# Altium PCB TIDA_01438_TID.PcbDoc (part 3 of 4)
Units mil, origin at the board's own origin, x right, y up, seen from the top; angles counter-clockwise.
Board outline 6250 x 2150 mil, 4 copper layers (Top Layer, V-, V+, Bottom Layer), stack 61.6 mil thick; 360 components, 217 nets, 1141 pads, 401 vias.
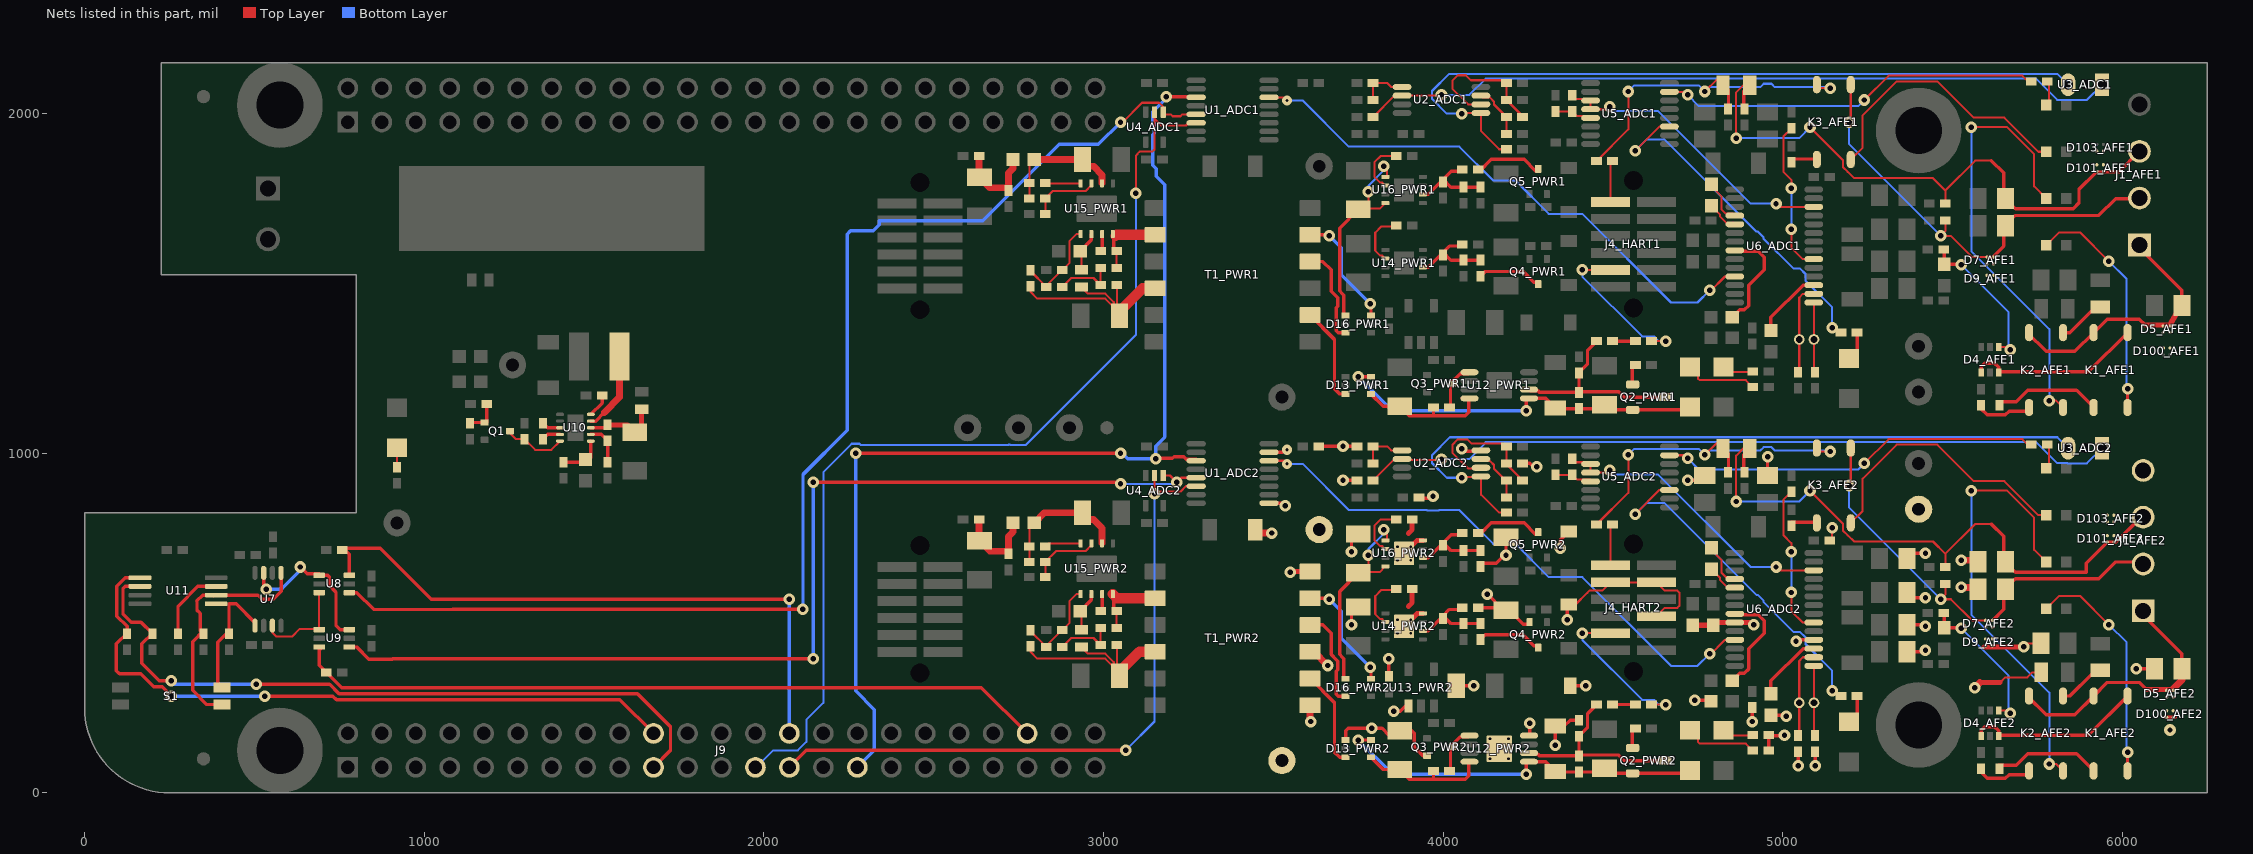
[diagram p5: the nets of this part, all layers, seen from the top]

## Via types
v1: diameter 34, hole 16, Top Layer to Bottom Layer, 337 vias
v2: diameter 19.68, hole 7.87, Top Layer to Bottom Layer, 36 vias
v3: diameter 39.37, hole 19.68, Top Layer to Bottom Layer, 24 vias
v4: diameter 30, hole 10, Top Layer to Bottom Layer, 4 vias

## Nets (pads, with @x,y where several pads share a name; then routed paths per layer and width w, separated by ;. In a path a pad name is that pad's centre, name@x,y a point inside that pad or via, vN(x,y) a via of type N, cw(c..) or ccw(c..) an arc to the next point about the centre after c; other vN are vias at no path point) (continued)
GND_ADC2: C1_ADC2.2 C4_ADC2.2 C6_ADC2.2 C7_ADC2.2 C8_ADC2.2 C12_ADC2.2 C13_ADC2.2 C14_ADC2.2 C16_ADC2.2 C17_AFE2.2 C19_AFE2.1 C20_AFE2.2 C21_AFE2.2 C22_AFE2.2 C23_AFE2.2 C25_AFE2.1 C27_AFE2.2 C28_AFE2.2 C30_AFE2.1 C40_PWR2.2 C41_PWR2.2 C43_PWR2.2 C44_PWR2.2 C46_PWR2.2 C47_PWR2.2 C48_PWR2.2 C52_PWR2.2 C58_PWR2.2 C59_PWR2.2 C61_PWR2.1 D9_AFE2.B1 D9_AFE2.B2 D13_PWR2.1 D15_PWR2.2 D17_PWR2.2 D18_PWR2.1 D100_AFE2.B1 D100_AFE2.B2 D103_AFE2.B1 D103_AFE2.B2 J1_AFE2.4 J4_HART2.3 J4_HART2.4 J4_HART2.8 Q3_PWR2.2 Q4_PWR2.2 R7_ADC2.1 R8_ADC2.2 R9_ADC2.1 R19_AFE2.1 R27_AFE2.1 R50_PWR2.1 R53_PWR2.1 R54_PWR2.2 R56_PWR2.1 R69_PWR2.1 T1_PWR2.7 T1_PWR2.9 T1_PWR2.12 TP4_AFE2.1 TP5_AFE2.1 TP6_AFE2.1 U1_ADC2.9 U1_ADC2.15 U2_ADC2.4 U6_ADC2.9 U6_ADC2.18 U12_PWR2.4 U12_PWR2.9 U13_PWR2.1 U14_PWR2.4 U14_PWR2.9 U16_PWR2.4 U16_PWR2.9 | length 4395
  Top Layer w6: D17_PWR2.2@4370,554.48 4389.47,554.47 4424.07,589.07 4424.13,589.07 4430.5,595.44 4467.92,595.44 J4_HART2.3@4492.48,620 J4_HART2.4@4627.52,620 4652.08,595.44 4689.5,595.44 4695.87,589.07 4695.87,550.93 4689.5,544.56 4652.08,544.56 J4_HART2.8@4627.52,520 ; R27_AFE2.1@5138.62,742.76 5145,749.13 v1(5145,780) ; 5640,325 5655,340 5720,340 5735,355 R19_AFE2.1@5760.63,355 ; v1@5710,440 C21_AFE2.2@5760,440
  Top Layer w10: U1_ADC2.9@3487.28,852.82 3537.5,852.82 3535,850.32 v1(3535,845) ; U1_ADC2.15@3487.28,1002.82 3527.5,1002.82 3540,1015.32 v4(3540,1010.32) ; v1@3607.95,212.05 v1(3610,210) ; C1_ADC2.2@3633.62,1020 v1(3705,1020) R8_ADC2.2@3746.38,1020 ; v1(3705,920) R7_ADC2.1@3746.38,920 ; D13_PWR2.1@3712.6,155.59 3712.6,182.6 3720,190 v1(3790,190) 3820,190 3840,170 3871.86,201.86 C41_PWR2.2@3871.86,182.9 3907.1,182.9 3915,175 3915,135 3940.59,109.41 Q3_PWR2.2@3958.5,109.41 ; v1(3730,495) 3730,545 3750,565 C47_PWR2.2@3750,547.09 ; v1(3730,710) 3730,745 3754.59,769.59 3762.09,762.09 C58_PWR2.2@3750,762.09 ; C43_PWR2.2@3840,341.5 3835,346.5 3840,351.5 v1(3840,395) ; U16_PWR2.9@3885,705 v2(3904.69,724.68) ; U13_PWR2.1@3897.6,255.87 3890,255.87 3874.13,240 v1(3855,240) ; C4_ADC2.2@3928.62,867.74 v1@3970,867.74 ; C44_PWR2.2@4037.91,315 v1(4090,315) ; v1(4055,1012.74) 4060,1012.74 4066.61,1006.13 U2_ADC2.4@4111.14,1006.13 ; R56_PWR2.1@4103.62,545 C46_PWR2.2@4170,545 ; R69_PWR2.1@4110,666.38 4110,676.38 4156.38,676.38 4185,705 C52_PWR2.2@4185,752.09 ; v1(4130,585) 4135,585 4135,580 C46_PWR2.2@4170,545 ; C46_PWR2.2@4185,537.09 4182.91,537.09 4175,545 C46_PWR2.2@4170,545 ; C46_PWR2.2@4190,542.09 4235.59,496.5 Q4_PWR2.2@4254.41,496.5 ; R9_ADC2.1@4233.62,970 4255,970 v1@4269.31,955.69 ; U12_PWR2.4@4252.6,168.39 4251.61,168.39 4255,171.77 v1(4255,205) ; v1@4270,955 v1@4269.31,955.69 ; v1(4275,960) 4275,961.38 v1@4269.31,955.69 ; v1(4330,140) C40_PWR2.2@4330,196.93 4356.93,196.93 4373.62,213.62 R53_PWR2.1@4400,213.62 R53_PWR2.1@4393.62,220 ; v1(4345,720) 4345,744.47 D18_PWR2.1@4370,769.47 ; v1(4365,510) 4365,549.47 D17_PWR2.2@4370,554.48 ; D15_PWR2.2@4374.46,315 v1(4420,315) ; v1(4720,920) 4755,920 C28_AFE2.2@4770,935 C28_AFE2.2@4775,935 ; v1(4741.09,273.13) 4785.38,273.13 C6_ADC2.2@4788.5,270 ; v1(4910,210) 4910,244.07 C7_ADC2.2@4911.3,245.37 ; C30_AFE2.1@4950,945 4950,935 C30_AFE2.1@4955,935 v1(4955,990) ; R50_PWR2.1@4958.62,125 R54_PWR2.2@4958.62,170 4960,168.62 5003.62,168.62 v1(5005,170) ; C16_ADC2.2@4965,228.5 5006.5,228.5 v1(5010,225) ; v1(5038.9,446.15) 5038.9,448.9 5040.43,450.43 U6_ADC2.18@5091.14,450.43 ; v1(5045,80) C12_ADC2.2@5045,121.38 ; v1(5095,80) C13_ADC2.2@5095,121.38 ; C25_AFE2.1@5350.01,690.01 C25_AFE2.1@5370,710 ; C17_AFE2.2@5364.45,393.52 5364.45,400 C17_AFE2.2@5364.45,403.52 ; C19_AFE2.1@5364.45,503.52 C19_AFE2.1@5364.45,508.49 ; C17_AFE2.2@5365,415 5420,415 v1(5420,420) ; C19_AFE2.1@5365,495 5420,495 v1(5420,490) ; C22_AFE2.2@5365,590 5370.03,584.97 5370.03,570 5380.03,580 5385.03,575 v1(5420,575) ; C25_AFE2.1@5365,690 5370,690 5385,705 v1(5420,705) ; v1@5706.84,433.16 v1(5710,430) ; v1(6040,365) C20_AFE2.2@6095,365 ; 6124.62,222.4 6155.22,222.4 ; v1(3855,240) 3854.57,239.57 3855,239.13 v1(3855,240)
  Top Layer w15: v1(3550,650) 3551.85,651.85 T1_PWR2.12@3607.95,651.85 ; U14_PWR2.9@3885,490 3923.39,528.39 U14_PWR2.4@3940.12,528.39 ; 3897.8,549.06 3908.62,559.88 C48_PWR2.2@3908.62,600 ; 3897.8,764.06 3908.62,774.88 C59_PWR2.2@3908.62,805 ; v2(3904.69,724.68) 3923.39,743.39 U16_PWR2.4@3940.12,743.39 ; C8_ADC2.2@4735,493.5 C14_ADC2.2@4795,493.5 4803.11,501.61 U6_ADC2.9@4858.86,501.61 4903.39,501.61 4910,495 v1(4915,495) ; 5580,325 5640,325 ; 5592.36,429 v1@5705,429
  Top Layer w20: C61_PWR2.1@3446.95,765 v1(3495,765) ; v1@3607.95,212.05 T1_PWR2.7@3607.95,258.15 ; T1_PWR2.9@3607.95,415.63 3619.37,415.63 v1(3660,375) ; v1(5525,605) C23_AFE2.2@5575,605 ; v1(5525,685) C27_AFE2.2@5575,685 ; v1(5565,310) 5580,325
  other v1: 6140,185 4185,700 3970,872.74
  other v2: 4137.83,100.87 4192.17,100.87 4165,130 4137.83,159.13 4192.17,159.13 3865.31,470.32 3904.69,470.32 3865.31,509.68 3904.69,509.68 3865.31,685.32 3904.69,685.32 3865.31,724.68
GPIO2_ADC1: R11_ADC1.1 U5_ADC1.11 U5_ADC1.12 U6_ADC1.26 | length 868.8
  Top Layer w6: R11_ADC1.1@4380,2053.62 4390.24,2043.39 4433.86,2043.39 U5_ADC1.11@4433.86,2038.39 U5_ADC1.12@4433.86,2017.8 ; U5_ADC1.12@4433.86,2012.8 v1@4492.8,2012.8 ; v1(4980,1735) 4989.84,1725.16 U6_ADC1.26@5091.14,1725.16
  Bottom Layer w6: v1(4490,2020) 4490,2015 4497.13,2007.87 4632.13,2007.87 4905,1735 v1(4980,1735)
GPIO2_ADC2: R11_ADC2.1 U5_ADC2.11 U5_ADC2.12 U6_ADC2.26 | length 868.8
  Top Layer w6: R11_ADC2.1@4380,983.62 4390.24,973.39 4433.86,973.39 U5_ADC2.11@4433.86,968.39 U5_ADC2.12@4433.86,947.8 ; U5_ADC2.12@4433.86,942.8 v1@4492.8,942.8 ; v1(4980,665) 4989.84,655.16 U6_ADC2.26@5091.14,655.16
  Bottom Layer w6: v1(4490,950) 4490,945 4497.13,937.87 4632.13,937.87 4905,665 v1(4980,665)
HART_IN_AFE1: C26_AFE1.2 J4_HART1.1 | length 122.5
  Top Layer w6: J4_HART1.1@4492.48,1740 4492.48,1853.86 C26_AFE1.2@4498.62,1860
HART_IN_AFE2: C26_AFE2.2 J4_HART2.1 | length 122.5
  Top Layer w6: J4_HART2.1@4492.48,670 4492.48,783.86 C26_AFE2.2@4498.62,790
HART_OUT_HART1: C42_PWR1.2 J4_HART1.9 | length 467.6
  Top Layer w6: v1(4410,1540) J4_HART1.9@4492.48,1540 ; C42_PWR1.2@4613.62,1330 v1(4655,1330)
  Bottom Layer w6: v1(4410,1540) 4410,1520 4586.13,1343.87 4621.33,1343.87 4635.2,1330 v1(4655,1330)
HART_OUT_HART2: C42_PWR2.2 J4_HART2.9 | length 467.6
  Top Layer w6: v1(4410,470) J4_HART2.9@4492.48,470 ; C42_PWR2.2@4613.62,260 v1(4655,260)
  Bottom Layer w6: v1(4410,470) 4410,450 4586.13,273.87 4621.33,273.87 4635.2,260 v1(4655,260)
I2C_A0: R35.2 S1.4 U7.1 U11.1 | length 368.1
  Top Layer w10: S1.4@405,310 391.43,323.57 391.43,442.92 R35.2@421.08,472.57 ; R35.2@425,468.65 425,556.63 446.12,556.63 U7.1@501.63,501.12
I2C_A1: R34.2 S1.3 U7.5 U11.2 | length 703.3
  Top Layer w10: R34.2@340.02,476.51 340.02,528.16 330.88,537.29 330.88,564.12 330,565 347.2,582.2 U11.2@377.23,582.2 ; R34.2@350.02,476.51 318.44,444.94 318.44,301.56 360,260 S1.3@405,260 ; U11.2@379.44,580 U11.2@377.23,582.2 ; U7.5@578.4,638.91 578.4,593.4 555.13,570.13 522.63,570.13 510.55,582.2 U11.2@387.2,582.2 U11.2@377.23,582.2
I2C_CLK: J9.19 R37.2 U11.6 | length 2121.3
  Top Layer w10: U11.6@162.8,607.8 119.13,607.8 112.87,601.54 112.87,527.4 137.65,502.62 166.03,502.62 199.28,469.37 R37.2@200.01,468.64 ; R37.2@200.01,476.51 200.01,470.11 168.44,438.54 168.44,380.96 219.7,329.7 254.7,329.7 v1(255,330) ; v1(505,320) 721.1,320 748.97,292.13 1627.87,292.13 1725,195 1725,125 J9.19@1675,75
  Bottom Layer w10: v1(255,330) 265,320 v1(505,320)
I2C_SDA: J9.20 R38.2 U11.5 | length 2001
  Top Layer w10: U11.5@152.81,633.4 119.46,633.4 95,608.94 95,520 125.01,489.98 125.01,470.11 93.44,438.54 93.44,359.34 102.66,350.13 164.78,350.13 203.08,311.83 228.17,311.83 v1(255,285) ; v1(530,285) 730.82,285 741.57,274.25 1575.75,274.25 J9.20@1675,175
  Bottom Layer w10: v1(255,285) v1(530,285)
LMT01_OUT1: J9.25 U1_ADC1.6 U4_ADC1.2 | length 2929.5
  Top Layer w6: v1(3095,1765) 3100,1765 3100,1770 3095,1775 3095,1875 3099.76,1879.76 3099.76,1881.32 3106.13,1887.68 3143.55,1887.68 3150,1894.13 3150,1985 ; U4_ADC1.2@3150,2004.29 3150,1985 ; U1_ADC1.6@3272.72,1972.82 3250.53,1972.82 3242.72,1965 3170,1965 3150,1985
  Bottom Layer w6: J9.25@1975,75 1977.45,75 2027.45,125 2100,125 2125,150 2125,215 2175,265 2175,944.42 2258.45,1027.87 2281.55,1027.87 2285.29,1024.13 2719.13,1024.13 2720,1025 2724.03,1025 2724.9,1024.13 2771.07,1024.13 3095,1348.05 v1(3095,1765)
LMT01_OUT2: J9.27 U1_ADC2.6 U4_ADC2.2 | length 1997.4
  Top Layer w6: U4_ADC2.2@3150,944.29 U4_ADC2.2@3150,934.29 v1(3150,880) 3157.13,887.13 3226.55,887.13 3242.23,902.82 U1_ADC2.6@3272.72,902.82
  Top Layer w10: J9.27@2075,75 2125,125 v1(3065,125)
  Bottom Layer w6: v1(3065,125) 3150,210 v1(3150,880)
NetC10_ADC1_1: C10_ADC1.1 R11_ADC1.2 U5_ADC1.13 | length 109.7
  Top Layer w6: C10_ADC1.1@4330,2006.38 R11_ADC1.2@4380,2006.38 4394.17,1992.2 U5_ADC1.13@4433.86,1992.2
NetC10_ADC2_1: C10_ADC2.1 R11_ADC2.2 U5_ADC2.13 | length 109.7
  Top Layer w6: C10_ADC2.1@4330,936.38 R11_ADC2.2@4380,936.38 4394.17,922.2 U5_ADC2.13@4433.86,922.2
NetC11_ADC1_1: C11_ADC1.1 U6_ADC1.4 | length 132.8
  Top Layer w6: C11_ADC1.1@4790,1791.5 4805,1776.5 4805,1770 4820,1755 4820,1717.41 4831.98,1705.43 4853,1705.43 U6_ADC1.4@4858.86,1699.57
NetC11_ADC1_2: C11_ADC1.2 U6_ADC1.5 | length 108.2
  Top Layer w6: C11_ADC1.2@4785,1728.5 4789.28,1728.5 4815.24,1702.54 4815.24,1696.57 4837.84,1673.98 U6_ADC1.5@4858.86,1673.98 U6_ADC1.5@4853,1679.83
NetC11_ADC2_1: C11_ADC2.1 U6_ADC2.4 | length 132.8
  Top Layer w6: C11_ADC2.1@4790,721.5 4805,706.5 4805,700 4820,685 4820,647.41 4831.98,635.43 4853,635.43 U6_ADC2.4@4858.86,629.57
NetC11_ADC2_2: C11_ADC2.2 U6_ADC2.5 | length 108.2
  Top Layer w6: C11_ADC2.2@4785,658.5 4789.28,658.5 4815.24,632.54 4815.24,626.57 4837.84,603.98 U6_ADC2.5@4858.86,603.98 U6_ADC2.5@4853,609.83
NetC12_ADC1_1: C12_ADC1.1 U6_ADC1.16 Y1_ADC1.1 | length 262.6
  Top Layer w6: C12_ADC1.1@5043.62,1245 5048.35,1249.72 Y1_ADC1.1@5048.35,1335 5048.35,1458.35 5059.25,1469.25 U6_ADC1.16@5091.14,1469.25
NetC12_ADC2_1: C12_ADC2.1 U6_ADC2.16 Y1_ADC2.1 | length 262.6
  Top Layer w6: C12_ADC2.1@5043.62,175 5048.35,179.72 Y1_ADC2.1@5048.35,265 5048.35,388.35 5059.25,399.25 U6_ADC2.16@5091.14,399.25
NetC13_ADC1_1: C13_ADC1.1 U6_ADC1.15 Y1_ADC1.2 | length 200.8
  Top Layer w6: U6_ADC1.15@5091.14,1443.66 5091.65,1443.15 Y1_ADC1.2@5091.65,1335 5091.65,1249.72 C13_ADC1.1@5096.38,1245
NetC13_ADC2_1: C13_ADC2.1 U6_ADC2.15 Y1_ADC2.2 | length 200.8
  Top Layer w6: U6_ADC2.15@5091.14,373.66 5091.65,373.15 Y1_ADC2.2@5091.65,265 5091.65,179.72 C13_ADC2.1@5096.38,175
NetC15_ADC1_1: C15_ADC1.1 U6_ADC1.8 | length 318
  Top Layer w10: C15_ADC1.1@4851.5,1400 4873.43,1421.93 4886.56,1421.93 4899.29,1434.66 4899.29,1494.54 4944.87,1540.13 4944.87,1577.37 4927.37,1594.87 4861.19,1594.87 U6_ADC1.8@4858.86,1597.2
NetC15_ADC2_1: C15_ADC2.1 U6_ADC2.8 | length 318
  Top Layer w10: C15_ADC2.1@4851.5,330 4873.43,351.93 4886.56,351.93 4899.29,364.66 4899.29,424.54 4944.87,470.13 4944.87,507.37 4927.37,524.87 4861.19,524.87 U6_ADC2.8@4858.86,527.2
NetC16_ADC1_1: C16_ADC1.1 U6_ADC1.17 | length 209.4
  Top Layer w10: C16_ADC1.1@4965,1361.5 4965,1400 5059.84,1494.84 U6_ADC1.17@5091.14,1494.84 U6_ADC1.17@5095,1490.98
NetC16_ADC2_1: C16_ADC2.1 U6_ADC2.17 | length 209.4
  Top Layer w10: C16_ADC2.1@4965,291.5 4965,330 5059.84,424.84 U6_ADC2.17@5091.14,424.84 U6_ADC2.17@5095,420.98
NetC20_AFE1_1: C20_AFE1.1 D5_AFE1.B1 D5_AFE1.B2 J1_AFE1.1 K1_AFE1.4 K2_AFE1.4 | length 742.3
  Top Layer w10: K2_AFE1.4@5720,1355.24 5775.24,1300 5859.76,1300 K1_AFE1.4@5915,1355.24 5954.76,1395 6050,1395 6067.48,1377.52 ; J1_AFE1.1@6061.04,1593.31 6175,1479.35 C20_AFE1.1@6175,1435
  Top Layer w15: 6067.48,1377.52 6144.76,1377.79 ; D5_AFE1.B1@6140,1377.78 C20_AFE1.1@6160.59,1415
NetC20_AFE2_1: C20_AFE2.1 D5_AFE2.B1 D5_AFE2.B2 J1_AFE2.1 K1_AFE2.4 K2_AFE2.4 | length 739.3
  Top Layer w10: K2_AFE2.4@5720,285.24 5775.24,230 5859.76,230 K1_AFE2.4@5915,285.24 5954.76,325 6050,325 6070.32,304.68 ; J1_AFE2.1@6061.04,523.31 6175,409.35 C20_AFE2.1@6175,365
  Top Layer w15: 6070.32,304.68 D5_AFE2.B1@6147.8,304.68
  Top Layer w20: 6150,307.52 6175,332.52
NetC23_AFE1_1: C23_AFE1.1 D7_AFE1.B1 D7_AFE1.B2 J1_AFE1.2 K3_AFE1.3 R21_AFE1.1 | length 1340.3
  Top Layer w6: v1(5195,1975) 5200,1980 K3_AFE1.3@5200,2085.24 ; R21_AFE1.1@5478.62,1685 5478.62,1653.62 v1(5465,1640) 5495,1640 5557.68,1577.32 D7_AFE1.B2@5601.16,1577.32
  Top Layer w10: D7_AFE1.B2@5605,1577.52 5617.52,1577.52 5650,1610 5650,1675 5665,1675 5665,1680 5685,1700 5930,1700 5979.8,1749.8 J1_AFE1.2@6061.04,1749.8
  Bottom Layer w6: v1(5195,1975) 5195,1910 v1(5465,1640)
NetC23_AFE2_1: C23_AFE2.1 D7_AFE2.B1 D7_AFE2.B2 J1_AFE2.2 K3_AFE2.3 R21_AFE2.1 | length 1344.1
  Top Layer w6: v1(5195,905) 5200,910 K3_AFE2.3@5200,1015.24 ; R21_AFE2.1@5478.62,615 5478.62,583.62 v1(5465,570) 5495,570 5557.48,507.52 D7_AFE2.B1@5617.52,507.52
  Top Layer w10: D7_AFE2.B1@5617.52,507.52 5650,540 5650,605 5665,605 5665,610 5685,630 5930,630 5979.8,679.8 J1_AFE2.2@6061.04,679.8
  Bottom Layer w6: v1(5195,905) 5195,840 v1(5465,570)
NetC26_AFE1_1: C26_AFE1.1 K3_AFE1.4 R24_AFE1.1 R25_AFE1.2 | length 1072.2
  Top Layer w6: C26_AFE1.1@4451.38,1860 4545,1953.62 v1(4545,2065) ; v1(4770,2065) 4805,2100 4806.97,2100 R25_AFE1.2@4823.21,2083.76 ; K3_AFE1.4@5095,2085.24 5095,2080 5100,2075 v1(5140,2075)
  Top Layer w10: R25_AFE1.2@4823.21,2083.76 4840,2066.97 R24_AFE1.1@4840,2013.62
  Bottom Layer w6: v1(4545,2065) 4562.87,2082.87 4752.13,2082.87 v1(4770,2065) 4782.87,2077.87 4933.45,2077.87 4943.45,2087.87 4966.55,2087.87 4976.55,2077.87 5132.13,2077.87 5135,2075 v1(5140,2075)
NetC26_AFE2_1: C26_AFE2.1 K3_AFE2.4 R24_AFE2.1 R25_AFE2.2 | length 1072.2
  Top Layer w6: C26_AFE2.1@4451.38,790 4545,883.62 v1(4545,995) ; v1(4770,995) 4805,1030 4806.97,1030 R25_AFE2.2@4823.21,1013.76 ; K3_AFE2.4@5095,1015.24 5095,1010 5100,1005 v1(5140,1005)
  Top Layer w10: R25_AFE2.2@4823.21,1013.76 4840,996.97 R24_AFE2.1@4840,943.62
  Bottom Layer w6: v1(4545,995) 4562.87,1012.87 4752.13,1012.87 v1(4770,995) 4782.87,1007.87 4933.45,1007.87 4943.45,1017.87 4966.55,1017.87 4976.55,1007.87 5132.13,1007.87 5135,1005 v1(5140,1005)
NetC27_AFE1_1: C27_AFE1.1 D101_AFE1.B1 D101_AFE1.B2 J1_AFE1.3 R22_AFE1.1 R25_AFE1.1 R26_AFE1.1 | length 1831.6
  Top Layer w6: 4862.69,2062.68 4862.69,1932.32 v1@4867.13,1927.87 ; v1(4862.77,1927.87) v1@4867.13,1927.87 ; 4863,2063 4883.76,2083.76 R25_AFE1.1@4902.58,2083.76 R25_AFE1.1@4912.63,2073.71 ; v1@4870,1925 v1@4867.13,1927.87 ; v1(5080,1960) 5177.31,1862.68 5177.31,1841.59 5190.6,1828.3 5191.7,1828.3 5210,1810 5442.24,1810 5478.62,1773.62 ; R22_AFE1.1@5478.62,1735 5478.62,1773.62 ; 5614.07,1861.55 5566.55,1861.55 5478.62,1773.62 ; C27_AFE1.1@5650,1755 C27_AFE1.1@5652.5,1752.5
  Top Layer w10: R26_AFE1.1@4885,2013.62 4885,2065.55 R25_AFE1.1@4897.22,2077.78 ; 5614.07,1861.55 5650,1825.62 C27_AFE1.1@5650,1755 ; C27_AFE1.1@5655,1750 5685,1720 5854.59,1720 5872,1737.41 5872,1777.3 5922.57,1827.87 5989.01,1827.87 J1_AFE1.3@6050.04,1888.9
  Bottom Layer w6: v1(4862.77,1927.87) 5047.87,1927.87 v1(5080,1960)
NetC27_AFE2_1: C27_AFE2.1 D101_AFE2.B1 D101_AFE2.B2 J1_AFE2.3 R22_AFE2.1 R25_AFE2.1 R26_AFE2.1 | length 1880.1
  Top Layer w6: 4862.69,992.68 4862.69,862.32 v1@4867.13,857.87 ; v1(4862.77,857.87) v1@4867.13,857.87 ; 4863,993 4883.76,1013.76 R25_AFE2.1@4902.58,1013.76 R25_AFE2.1@4912.63,1003.71 ; v1@4870,855 v1@4867.13,857.87 ; v1(5080,890) 5177.31,792.68 5177.31,771.59 5190.6,758.3 5191.7,758.3 5210,740 5442.24,740 5478.62,703.62 ; R22_AFE2.1@5478.62,665 5478.62,703.62 ; 5614.07,791.55 5566.55,791.55 5478.62,703.62 ; C27_AFE2.1@5650,685 C27_AFE2.1@5652.5,682.5
  Top Layer w10: R26_AFE2.1@4885,943.62 4885,995.55 R25_AFE2.1@4897.22,1007.78 ; 5614.07,791.55 5650,755.62 C27_AFE2.1@5650,685 ; C27_AFE2.1@5655,680 5685,650 5893.44,650 5893.44,675.92 D101_AFE2.B1@5955.16,737.63 D101_AFE2.B2@5974.84,737.63 5980.18,737.63 6048.81,806.26 6048.81,811.6 J1_AFE2.3@6061.04,811.6 ; J1_AFE2.3@6044.94,809 6045.57,808.36 6051.69,802.25 J1_AFE2.3@6061.04,792.9 ; J1_AFE2.3@6044.94,815 6048.57,811.36 6054.69,805.25 J1_AFE2.3@6061.04,798.9
  Bottom Layer w6: v1(4862.77,857.87) 5047.87,857.87 v1(5080,890)
NetC36_1: C36.1 U10.4 | length 55.5
  Top Layer w10: C36.1@1350,1041.38 1363.94,1055.32 U10.4@1399.72,1055.32
NetC36_2: C36.2 U10.3 | length 55.4
  Top Layer w10: C36.2@1350,1088.62 1363.62,1075 U10.3@1399.72,1075
NetC37_1: C37.1 R43.1 U10.6 | length 124.6
  Top Layer w10: R43.1@1410,973.62 1467.13,973.62 C37.1@1475,981.5 C37.1@1480.28,986.77 ; C37.1@1490.28,986.77 U10.6@1490.28,1035.63
NetC38_1: C38.1 U10.10 | length 69.4
  Top Layer w10: U10.10@1490.28,1114.37 1523.62,1147.72 C38.1@1523.62,1170
NetC39_1: C39.1 D10.2 R41.2 U10.8 | length 217.8
  Top Layer w10: U10.8@1490.28,1075 1531.38,1075 R41.2@1540,1083.62
  Top Layer w15: R41.2@1540,1083.62 1598.46,1083.62 C39.1@1620,1062.09 1640,1082.09 D10.2@1640,1129.41
NetC40_PWR1_1: C40_PWR1.1 D12_PWR1.2 D13_PWR1.6 Q2_PWR1.2 R46_PWR1.2 R48_PWR1.1 U12_PWR1.1 | length 1095.1
  Top Layer w10: v1(3750,1225) 3750.59,1225.59 D13_PWR1.6@3787.4,1225.59 ; v1(4245,1125) 4245,1154.02 U12_PWR1.1@4252.6,1161.61 4301.46,1161.61 C40_PWR1.1@4330,1133.07 ; C40_PWR1.1@4343.46,1146.54 4358.62,1131.38 R48_PWR1.1@4400,1131.38 4463.46,1131.38 R46_PWR1.2@4475,1142.91 4490.31,1127.6 Q2_PWR1.2@4557.76,1127.6 D12_PWR1.2@4718.15,1127.6
  Bottom Layer w10: v1(3750,1225) 3845,1130 3850,1125 v1(4245,1125)
NetC40_PWR2_1: C40_PWR2.1 D12_PWR2.2 D13_PWR2.6 Q2_PWR2.2 R46_PWR2.2 R48_PWR2.1 U12_PWR2.1 | length 1095.1
  Top Layer w10: v1(3750,155) 3750.59,155.59 D13_PWR2.6@3787.4,155.59 ; v1(4245,55) 4245,84.02 U12_PWR2.1@4252.6,91.61 4301.46,91.61 C40_PWR2.1@4330,63.07 ; C40_PWR2.1@4343.46,76.54 4358.62,61.38 R48_PWR2.1@4400,61.38 4463.46,61.38 R46_PWR2.2@4475,72.91 4490.31,57.6 Q2_PWR2.2@4557.76,57.6 D12_PWR2.2@4718.15,57.6
  Bottom Layer w10: v1(3750,155) 3845,60 3850,55 v1(4245,55)
NetC41_PWR1_1: C41_PWR1.1 D13_PWR1.4 R47_PWR1.1 U12_PWR1.8 | length 407.7
  Top Layer w10: D13_PWR1.4@3787.4,1174.41 3823.08,1138.73 C41_PWR1.1@3871.86,1138.73 3900.58,1110 3970,1110 ; R47_PWR1.1@3971.38,1135 3971.38,1111.38 3970,1110 ; U12_PWR1.8@4056.28,1161.61 U12_PWR1.8@4077.4,1161.61 4075,1159.21 4075,1120 4065,1110 3970,1110
NetC41_PWR2_1: C41_PWR2.1 D13_PWR2.4 R47_PWR2.1 U12_PWR2.8 | length 407.7
  Top Layer w10: D13_PWR2.4@3787.4,104.41 3823.08,68.73 C41_PWR2.1@3871.86,68.73 3900.58,40 3970,40 ; R47_PWR2.1@3971.38,65 3971.38,41.38 3970,40 ; U12_PWR2.8@4056.28,91.61 U12_PWR2.8@4077.4,91.61 4075,89.21 4075,50 4065,40 3970,40
NetC42_PWR1_1: C42_PWR1.1 R52_PWR1.2 | length 67.8
  Top Layer w10: R52_PWR1.2@4498.62,1330 C42_PWR1.1@4566.38,1330
NetC42_PWR2_1: C42_PWR2.1 R52_PWR2.2 | length 67.8
  Top Layer w10: R52_PWR2.2@4498.62,260 C42_PWR2.1@4566.38,260
NetC45_PWR1_2: C45_PWR1.2 R55_PWR1.1 R56_PWR1.2 R57_PWR1.1 U14_PWR1.2 | length 256.7
  Top Layer w10: U14_PWR1.2@3940.12,1547.2 3955.71,1547.2 C45_PWR1.2@4000,1591.5 ; R56_PWR1.2@4056.38,1610 4018.5,1610 C45_PWR1.2@4000,1591.5 ; R57_PWR1.1@4105,1568.62 4055,1568.62 4022.87,1568.62 C45_PWR1.2@4000,1591.5
NetC45_PWR2_2: C45_PWR2.2 R55_PWR2.1 R56_PWR2.2 R57_PWR2.1 U14_PWR2.2 | length 256.7
  Top Layer w10: U14_PWR2.2@3940.12,477.2 3955.71,477.2 C45_PWR2.2@4000,521.5 ; R56_PWR2.2@4056.38,540 4018.5,540 C45_PWR2.2@4000,521.5 ; R57_PWR2.1@4105,498.62 4055,498.62 4022.87,498.62 C45_PWR2.2@4000,521.5
NetC48_PWR1_1: C48_PWR1.1 U14_PWR1.6 | length 162.7
  Top Layer w6: U14_PWR1.6@3830,1572.8 U14_PWR1.6@3829.88,1572.8 3821.07,1581.61 3814.71,1581.61 3800,1596.31 3800,1649.42 3818.45,1667.87 3859.25,1667.87 C48_PWR1.1@3861.38,1670
NetC48_PWR2_1: C48_PWR2.1 U14_PWR2.6 | length 162.7
  Top Layer w6: U14_PWR2.6@3830,502.8 U14_PWR2.6@3829.88,502.8 3821.07,511.61 3814.71,511.61 3800,526.31 3800,579.42 3818.45,597.87 3859.25,597.87 C48_PWR2.1@3861.38,600
NetC49_PWR1_1: C49_PWR1.1 R59_PWR1.2 T1_PWR1.2 U15_PWR1.8 | length 214.7
  Top Layer w6: R59_PWR1.2@3038.62,1545 C49_PWR1.1@3038.62,1595
  Top Layer w10: U15_PWR1.8@3027.24,1645.2 3030,1642.44 C49_PWR1.1@3030,1600
  Top Layer w30: 3035,1640 3038.11,1643.11 T1_PWR1.2@3152.05,1643.11
NetC49_PWR1_2: C49_PWR1.2 U15_PWR1.7 | length 59.1
  Top Layer w10: C49_PWR1.2@2983.5,1595 2990,1595 2995.75,1600.75 U15_PWR1.7@2995.75,1645.2
NetC49_PWR2_1: C49_PWR2.1 R59_PWR2.2 T1_PWR2.2 U15_PWR2.8 | length 222.3
  Top Layer w6: R59_PWR2.2@3038.62,485 C49_PWR2.1@3038.62,535
  Top Layer w10: C49_PWR2.1@3030,540 U15_PWR2.8@3030,582.44
  Top Layer w30: U15_PWR2.8@3027.24,585.2 3030,582.44 3039.33,573.11 T1_PWR2.2@3152.05,573.11
NetC49_PWR2_2: C49_PWR2.2 U15_PWR2.7 | length 59.1
  Top Layer w10: C49_PWR2.2@2983.5,535 2990,535 2995.75,540.75 U15_PWR2.7@2995.75,585.2
NetC50_PWR1_1: C50_PWR1.1 C57_PWR1.1 D19_PWR1.2 R65_PWR1.2 T1_PWR1.4 | length 635.1
  Top Layer w6: R65_PWR1.2@2785,1491.38 2785,1475 2805,1455 3005,1455 3040,1420 C50_PWR1.1@3040,1493.62 ; D19_PWR1.2@2935,1488.35 2953.35,1470 3005,1470 3030,1445 C57_PWR1.1@3030,1435 ; C50_PWR1.1@3038.62,1495 C50_PWR1.1@3044.31,1489.31
  Top Layer w30: C57_PWR1.1@3045,1415 3115.63,1485.63 T1_PWR1.4@3152.05,1485.63
NetC50_PWR1_2: C50_PWR1.2 C56_PWR1.1 R59_PWR1.1 | length 182.2
  Top Layer w6: C56_PWR1.1@2878.62,1490 2904.56,1515.94 2970.44,1515.94 C50_PWR1.2@2991.38,1495 R59_PWR1.1@2991.38,1545
NetC50_PWR2_1: C50_PWR2.1 C57_PWR2.1 D19_PWR2.2 R65_PWR2.2 T1_PWR2.4 | length 609.7
  Top Layer w6: R65_PWR2.2@2785,431.38 2785,415 2805,395 3005,395 3040,360 C50_PWR2.1@3040,433.62 ; D19_PWR2.2@2935,428.35 2953.35,410 3005,410 3030,385 C57_PWR2.1@3030,375 ; C50_PWR2.1@3038.62,435 C50_PWR2.1@3040,433.62 ; C50_PWR2.1@3044.31,429.31 C50_PWR2.1@3040,433.62
  Top Layer w30: C57_PWR2.1@3060,370 3105.63,415.63 T1_PWR2.4@3152.05,415.63
NetC50_PWR2_2: C50_PWR2.2 C56_PWR2.1 R59_PWR2.1 | length 182.2
  Top Layer w6: C56_PWR2.1@2878.62,430 2904.56,455.94 2970.44,455.94 C50_PWR2.2@2991.38,435 R59_PWR2.1@2991.38,485
NetC51_PWR1_2: C51_PWR1.2 R60_PWR1.1 R66_PWR1.2 R69_PWR1.2 U16_PWR1.2 | length 258.8
  Top Layer w10: U16_PWR1.2@3940.12,1762.2 3955.71,1762.2 C51_PWR1.2@4000,1806.5 ; R66_PWR1.2@4056.38,1830 4023.5,1830 C51_PWR1.2@4000,1806.5 ; R69_PWR1.2@4105,1783.62 4055,1783.62 4022.87,1783.62 C51_PWR1.2@4000,1806.5
NetC51_PWR2_2: C51_PWR2.2 R60_PWR2.1 R66_PWR2.2 R69_PWR2.2 U16_PWR2.2 | length 258.8
  Top Layer w10: U16_PWR2.2@3940.12,692.2 3955.71,692.2 C51_PWR2.2@4000,736.5 ; R66_PWR2.2@4056.38,760 4023.5,760 C51_PWR2.2@4000,736.5 ; R69_PWR2.2@4105,713.62 4055,713.62 4022.87,713.62 C51_PWR2.2@4000,736.5
NetC53_PWR1_1: C53_PWR1.1 C54_PWR1.1 L2_PWR1.1 R62_PWR1.2 | length 251.5
  Top Layer w20: R62_PWR1.2@2633.62,1875 2633.62,1816.54 2632.09,1815 C53_PWR1.1@2635,1812.09 2665.59,1781.5 2720,1781.5 2720,1825 2733.5,1838.5 L2_PWR1.1@2733.5,1865
NetC53_PWR2_1: C53_PWR2.1 C54_PWR2.1 L2_PWR2.1 R62_PWR2.2 | length 251.5
  Top Layer w20: R62_PWR2.2@2633.62,805 2633.62,746.54 2632.09,745 C53_PWR2.1@2635,742.09 2665.59,711.5 2720,711.5 2720,755 2733.5,768.5 L2_PWR2.1@2733.5,795
NetC55_PWR1_1: C55_PWR1.1 L2_PWR1.2 R63_PWR1.2 R64_PWR1.2 U15_PWR1.2 | length 363.9
  Top Layer w6: R64_PWR1.2@2781.38,1750 R63_PWR1.2@2781.38,1795 2781.38,1849.88 L2_PWR1.2@2796.5,1865
  Top Layer w20: L2_PWR1.2@2796.5,1865 C55_PWR1.1@2937.91,1865 2957.91,1845 2970,1845 2995.75,1819.25 U15_PWR1.2@2995.75,1794.8
NetC55_PWR2_1: C55_PWR2.1 L2_PWR2.2 R63_PWR2.2 R64_PWR2.2 U15_PWR2.2 | length 396.3
  Top Layer w6: R64_PWR2.2@2781.38,680 R63_PWR2.2@2781.38,725 2781.38,779.88 L2_PWR2.2@2796.5,795
  Top Layer w20: L2_PWR2.2@2796.5,795 2826.5,825 C55_PWR2.1@2937.91,825 2957.91,805 2970,805 2995.75,779.25 U15_PWR2.2@2995.75,734.8
NetC56_PWR1_2: C56_PWR1.2 R65_PWR1.1 R68_PWR1.2 U15_PWR1.5 | length 272.5
  Top Layer w6: R65_PWR1.1@2785,1538.62 2785,1536.38 C56_PWR1.2@2831.38,1490 2831.38,1492.76 R68_PWR1.2@2878.62,1540 2900,1561.38 2900,1625.2 2920,1645.2 U15_PWR1.5@2932.76,1645.2
NetC56_PWR2_2: C56_PWR2.2 R65_PWR2.1 R68_PWR2.2 U15_PWR2.5 | length 272.5
  Top Layer w6: R65_PWR2.1@2785,478.62 2785,476.38 C56_PWR2.2@2831.38,430 2831.38,432.76 R68_PWR2.2@2878.62,480 2900,501.38 2900,565.2 2920,585.2 U15_PWR2.5@2932.76,585.2
NetC58_PWR1_1: C58_PWR1.1 D16_PWR1.1 U16_PWR1.5 U16_PWR1.8 | length 612.8
  Top Layer w6: C58_PWR1.1@3750,1725 C58_PWR1.1@3753.54,1721.46 ; v1(3780,1770) 3780,1730 3770,1720 3813.27,1720 U16_PWR1.8@3829.88,1736.61 ; U16_PWR1.5@3824.87,1816.29 U16_PWR1.5@3830.91,1816.29 ; v1(3825.17,1845) 3830,1845 3835,1840 3835,1818.5 U16_PWR1.5@3829.88,1813.39
  Top Layer w10: D16_PWR1.1@3712.6,1405.59 3707.75,1410.44 3707.75,1464.78 3702.87,1469.65 3702.87,1469.82 3695,1477.7 3695,1662.91 C58_PWR1.1@3750,1717.91
  Bottom Layer w6: v1(3780,1770) 3780,1787.89 3830,1837.89 3825,1842.89 3825.17,1843.06 v1(3825.17,1845)
NetC58_PWR2_1: C58_PWR2.1 D16_PWR2.1 U16_PWR2.5 U16_PWR2.8 | length 612.8
  Top Layer w6: C58_PWR2.1@3750,655 C58_PWR2.1@3753.54,651.46 ; v1(3780,700) 3780,660 3770,650 3813.27,650 U16_PWR2.8@3829.88,666.61 ; U16_PWR2.5@3824.87,746.29 U16_PWR2.5@3830.91,746.29 ; v1(3825.17,775) 3830,775 3835,770 3835,748.5 U16_PWR2.5@3829.88,743.39
  Top Layer w10: D16_PWR2.1@3712.6,335.59 3707.75,340.44 3707.75,394.78 3702.87,399.65 3702.87,399.83 3695,407.7 3695,592.91 C58_PWR2.1@3750,647.91
  Bottom Layer w6: v1(3780,700) 3780,717.89 3830,767.89 3825,772.89 3825.17,773.06 v1(3825.17,775)
NetC59_PWR1_1: C59_PWR1.1 U16_PWR1.6 | length 149.9
  Top Layer w6: U16_PWR1.6@3829.88,1787.8 3821.07,1796.61 3814.71,1796.61 3797.29,1814.02 3797.29,1856.71 3815.58,1875 C59_PWR1.1@3853.5,1875
NetC59_PWR2_1: C59_PWR2.1 U16_PWR2.6 | length 149.9
  Top Layer w6: U16_PWR2.6@3829.88,717.8 3821.07,726.61 3814.71,726.61 3797.29,744.02 3797.29,786.71 3815.58,805 C59_PWR2.1@3853.5,805
NetC60_PWR1_1: C60_PWR1.1 D19_PWR1.1 U15_PWR1.6 | length 128.6
  Top Layer w6: C60_PWR1.1@2931.5,1595 2935,1591.5 D19_PWR1.1@2935,1540.59 D19_PWR1.1@2935,1531.65
  Top Layer w10: C60_PWR1.1@2931.5,1595 2964.25,1627.76 U15_PWR1.6@2964.25,1645.2
NetC60_PWR2_1: C60_PWR2.1 D19_PWR2.1 U15_PWR2.6 | length 128.6
  Top Layer w6: C60_PWR2.1@2931.5,535 2935,531.5 D19_PWR2.1@2935,480.59 D19_PWR2.1@2935,471.65
  Top Layer w10: C60_PWR2.1@2931.5,535 2964.25,567.76 U15_PWR2.6@2964.25,585.2
NetD1_ADC1_1: D1_ADC1.1 R13_ADC1.2 | length 73
  Top Layer w6: D1_ADC1.1@5775.47,2025.4 5783.62,2033.55 R13_ADC1.2@5783.62,2095
NetD1_ADC2_1: D1_ADC2.1 R13_ADC2.2 | length 73
  Top Layer w6: D1_ADC2.1@5775.47,955.39 5783.62,963.55 R13_ADC2.2@5783.62,1025
NetD2_ADC1_2: D2_ADC1.2 R12_ADC1.2 | length 85.7
  Top Layer w10: D2_ADC1.2@5195,1279.06 5218.62,1302.68 R12_ADC1.2@5218.62,1355
NetD2_ADC2_2: D2_ADC2.2 R12_ADC2.2 | length 85.7
  Top Layer w10: D2_ADC2.2@5195,209.06 5218.62,232.68 R12_ADC2.2@5218.62,285
NetD3_AFE1_1: D3_AFE1.1 K1_AFE1.2 | length 688.5
  Top Layer w6: D3_AFE1.1@5775.47,1612.01 5813.46,1650 5875,1650 v1(5960,1565)
  Top Layer w10: K1_AFE1.2@6015,1134.76 v1(6015,1190)
  Bottom Layer w6: v1(5960,1565) 6012.13,1512.87 6012.13,1192.87 v1(6015,1190)
NetD3_AFE2_1: D3_AFE2.1 K1_AFE2.2 | length 688.5
  Top Layer w6: D3_AFE2.1@5775.47,542.01 5813.46,580 5875,580 v1(5960,495)
  Top Layer w10: K1_AFE2.2@6015,64.76 v1(6015,120)
  Bottom Layer w6: v1(5960,495) 6012.13,442.87 6012.13,122.87 v1(6015,120)
NetD4_AFE1_1: D4_AFE1.1 R16_AFE1.1 R17_AFE1.1 | length 442.2
  Top Layer w6: D4_AFE1.1@5635.59,1312.4 5662.6,1312.4 v1(5670,1305)
  Top Layer w10: R17_AFE1.1@5473.62,1600 5475,1598.62 R16_AFE1.1@5475,1556.5 5523.5,1556.5 v1(5525,1555)
  Bottom Layer w6: v1(5525,1555) 5665,1415 5665,1310 v1(5670,1305)
NetD4_AFE1_4: D4_AFE1.4 D4_AFE1.6 K1_AFE1.3 | length 517.3
  Top Layer w10: D4_AFE1.4@5584.41,1237.6 5584.41,1254.41 5595,1265 5623.19,1265 5635.59,1252.6 5635.59,1240 5899.76,1240 K1_AFE1.3@6015,1355.24
NetD4_AFE2_1: D4_AFE2.1 R16_AFE2.1 R17_AFE2.1 | length 442.2
  Top Layer w6: D4_AFE2.1@5635.59,242.4 5662.6,242.4 v1(5670,235)
  Top Layer w10: R17_AFE2.1@5473.62,530 5475,528.62 R16_AFE2.1@5475,486.5 5523.5,486.5 v1(5525,485)
  Bottom Layer w6: v1(5525,485) 5665,345 5665,240 v1(5670,235)
NetD4_AFE2_4: D4_AFE2.4 D4_AFE2.6 K1_AFE2.3 | length 517.3
  Top Layer w10: D4_AFE2.4@5584.41,167.6 5584.41,184.41 5595,195 5623.19,195 5635.59,182.6 5635.59,170 5899.76,170 K1_AFE2.3@6015,285.24
NetD5_AFE1_A1: D5_AFE1.A1 D5_AFE1.A2 D100_AFE1.A1 D100_AFE1.A2
NetD5_AFE2_A1: D5_AFE2.A1 D5_AFE2.A2 D100_AFE2.A1 D100_AFE2.A2
NetD6_AFE1_1: D6_AFE1.1 K2_AFE1.2 | length 1311.7
  Top Layer w6: v1(5555,1960) 5660.38,1960 5740,1880.38 5740,1785.47 D6_AFE1.1@5775.47,1750 ; v1(5785,1155) 5804.76,1155 K2_AFE1.2@5825,1134.76
  Bottom Layer w6: v1(5555,1960) 5555,1595 5785,1365 v1(5785,1155)
NetD6_AFE2_1: D6_AFE2.1 K2_AFE2.2 | length 1311.7
  Top Layer w6: v1(5555,890) 5660.38,890 5740,810.38 5740,715.47 D6_AFE2.1@5775.47,679.97 ; v1(5785,85) 5804.76,85 K2_AFE2.2@5825,64.76
  Bottom Layer w6: v1(5555,890) 5555,525 5785,295 v1(5785,85)
NetD7_AFE1_A1: D7_AFE1.A1 D7_AFE1.A2 D9_AFE1.A1 D9_AFE1.A2
NetD7_AFE2_A1: D7_AFE2.A1 D7_AFE2.A2 D9_AFE2.A1 D9_AFE2.A2
NetD8_AFE1_1: D8_AFE1.1 K3_AFE1.2 | length 817.5
  Top Layer w6: K3_AFE1.2@5195,1864.76 K3_AFE1.2@5200,1864.76 5235,1899.76 5235,1995 5335,2095 5455,2095 5562.13,1987.87 5652.12,1987.87 5752.4,1887.6 D8_AFE1.1@5775.47,1887.6
NetD8_AFE2_1: D8_AFE2.1 K3_AFE2.2 | length 817.5
  Top Layer w6: K3_AFE2.2@5195,794.76 K3_AFE2.2@5200,794.76 5235,829.76 5235,925 5335,1025 5455,1025 5562.13,917.87 5652.12,917.87 5752.4,817.6 D8_AFE2.1@5775.47,817.56
NetD11_1: D11.1 R45.2 | length 57.3
  Top Layer w6: R45.2@920,958.62 D11.1@920,1015.94
NetD12_PWR1_1: D12_PWR1.1 R50_PWR1.2 | length 215.5
  Top Layer w6: D12_PWR1.1@4726.5,1254.06 4750,1230.56 4750,1220 4755,1215 4891.38,1215 R50_PWR1.2@4911.38,1195
NetD12_PWR2_1: D12_PWR2.1 R50_PWR2.2 | length 215.5
  Top Layer w6: D12_PWR2.1@4726.5,184.06 4750,160.56 4750,150 4755,145 4891.38,145 R50_PWR2.2@4911.38,125
NetD13_PWR1_3: D13_PWR1.3 T1_PWR1.8 | length 295.9
  Top Layer w10: T1_PWR1.8@3618.11,1406.89 T1_PWR1.8@3607.95,1406.89 3680,1334.84 3680,1190 3695.59,1174.41 D13_PWR1.3@3712.6,1174.41
NetD13_PWR2_3: D13_PWR2.3 T1_PWR2.8 | length 295.9
  Top Layer w10: T1_PWR2.8@3618.11,336.89 T1_PWR2.8@3607.95,336.89 3680,264.84 3680,120 3695.59,104.41 D13_PWR2.3@3712.6,104.41
NetD14_PWR1_1: D14_PWR1.1 R54_PWR1.1 | length 88.3
  Top Layer w6: D14_PWR1.1@4845.43,1238.62 4910,1238.62 R54_PWR1.1@4911.38,1240
  Top Layer w10: D14_PWR1.1@4830,1254.06 D14_PWR1.1@4845.43,1238.62
NetD14_PWR2_1: D14_PWR2.1 R54_PWR2.1 | length 88.3
  Top Layer w6: D14_PWR2.1@4845.43,168.62 4910,168.62 R54_PWR2.1@4911.38,170
  Top Layer w10: D14_PWR2.1@4830,184.06 D14_PWR2.1@4845.43,168.62
NetD16_PWR1_3: D16_PWR1.3 T1_PWR1.10 | length 293.2
  Top Layer w10: T1_PWR1.10@3608.58,1565 T1_PWR1.10@3607.95,1564.37 3645.63,1564.37 3670,1540 3670,1477.42 3685,1462.42 3685,1462.25 3689.87,1457.37 3689.87,1432.63 3685,1427.75 3685,1360 3690.59,1354.41 D16_PWR1.3@3712.6,1354.41
NetD16_PWR1_6: D16_PWR1.6 T1_PWR1.11 | length 343.4
  Top Layer w10: T1_PWR1.11@3607.95,1643.11 3661.89,1643.11 v1(3665,1640) ; v1(3785,1440) 3785,1435 3787.4,1432.6 D16_PWR1.6@3787.4,1405.59
  Bottom Layer w10: v1(3665,1640) 3700.13,1604.87 3700.13,1524.87 v1(3785,1440)
NetD16_PWR2_3: D16_PWR2.3 T1_PWR2.10 | length 293.2
  Top Layer w10: T1_PWR2.10@3608.58,495 T1_PWR2.10@3607.95,494.37 3645.63,494.37 3670,470 3670,407.42 3685,392.42 3685,392.25 3689.87,387.37 3689.87,362.63 3685,357.75 3685,290 3690.59,284.41 D16_PWR2.3@3712.6,284.41
NetD16_PWR2_6: D16_PWR2.6 T1_PWR2.11 | length 343.4
  Top Layer w10: T1_PWR2.11@3607.95,573.11 3661.89,573.11 v1(3665,570) ; v1(3785,370) 3785,365 3787.4,362.6 D16_PWR2.6@3787.4,335.59
  Bottom Layer w10: v1(3665,570) 3700.13,534.87 3700.13,454.87 v1(3785,370)
NetD101_AFE1_A1: D101_AFE1.A1 D101_AFE1.A2 D103_AFE1.A1 D103_AFE1.A2
NetD101_AFE2_A1: D101_AFE2.A1 D101_AFE2.A2 D103_AFE2.A1 D103_AFE2.A2
NetK1_AFE1_1: K1_AFE1.1 R15_AFE1.2 | length 314.7
  Top Layer w10: R15_AFE1.2@5635,1151.38 5687.92,1151.38 5721.55,1185 5864.76,1185 K1_AFE1.1@5915,1134.76
NetK1_AFE2_1: K1_AFE2.1 R15_AFE2.2 | length 314.7
  Top Layer w10: R15_AFE2.2@5635,81.38 5687.92,81.38 5721.55,115 5864.76,115 K1_AFE2.1@5915,64.76
NetK2_AFE1_1: K2_AFE1.1 R20_AFE1.2 | length 159.2
  Top Layer w10: R20_AFE1.2@5583.35,1141.38 5583.35,1131.65 5602.24,1112.76 5655.49,1112.76 5666.24,1123.5 K2_AFE1.1@5718.74,1123.5 ; K2_AFE1.1@5718.74,1133.5 K2_AFE1.1@5720,1134.76
NetK2_AFE1_3: K2_AFE1.3 R18_AFE1.1 | length 117.7
  Top Layer w10: K2_AFE1.3@5820,1355.24 5845.24,1355.24 R18_AFE1.1@5910.63,1420.63
NetK2_AFE2_1: K2_AFE2.1 R20_AFE2.2 | length 159.2
  Top Layer w10: R20_AFE2.2@5583.35,71.38 5583.35,61.65 5602.24,42.76 5655.49,42.76 5666.24,53.5 K2_AFE2.1@5718.74,53.5 ; K2_AFE2.1@5718.74,63.5 K2_AFE2.1@5720,64.76
NetK2_AFE2_3: K2_AFE2.3 R18_AFE2.1 | length 117.7
  Top Layer w10: K2_AFE2.3@5820,285.24 5845.24,285.24 R18_AFE2.1@5910.63,350.63
NetK3_AFE1_1: K3_AFE1.1 R23_AFE1.2 | length 70.7
  Top Layer w10: R23_AFE1.2@5025,1866.38 5093.39,1866.38 K3_AFE1.1@5095,1864.76
NetK3_AFE2_1: K3_AFE2.1 R23_AFE2.2 | length 70.7
  Top Layer w10: R23_AFE2.2@5025,796.38 5093.39,796.38 K3_AFE2.1@5095,794.76
NetL1_2: L1.2 U10.9 | length 186.3
  Top Layer w10: U10.9@1490.28,1094.69 1504.69,1094.69 1530,1120
  Top Layer w20: 1530,1120 1575,1165 1575,1220 L1.2@1587.32,1232.32
NetQ1_1: Q1.1 R40.1 R42.2 | length 103.8
  Top Layer w10: R42.2@1135,1088.62 1136.97,1090.59 1183.5,1090.59 1183.5,1144.88 R40.1@1183.62,1145
NetQ1_3: Q1.3 R39.1 U10.5 | length 186.6
  Top Layer w6: Q1.3@1246.5,1065 1270.12,1041.38 R39.1@1295,1041.38 1326.38,1010 1374.09,1010 U10.5@1399.72,1035.63
NetQ2_PWR1_1: Q2_PWR1.1 R49_PWR1.1 | length 58.2
  Top Layer w10: R49_PWR1.1@4556.38,1260 4556.38,1203.78 Q2_PWR1.1@4557.76,1202.4
NetQ2_PWR1_3: Q2_PWR1.3 R48_PWR1.2 R52_PWR1.1 R53_PWR1.2 U12_PWR1.2 | length 583.8
  Top Layer w10: U12_PWR1.2@4252.6,1187.2 4256.46,1183.35 4279.32,1183.35 4283.18,1179.49 4399.13,1179.49 R48_PWR1.2@4400,1178.62 ; R52_PWR1.1@4451.38,1330 4425,1303.62 4425,1262.86 4400,1237.86 R53_PWR1.2@4400,1236.38 R48_PWR1.2@4400,1178.62 ; Q2_PWR1.3@4652.24,1165 4533.13,1165 4516.75,1181.38 4402.76,1181.38 R48_PWR1.2@4400,1178.62
NetQ2_PWR2_1: Q2_PWR2.1 R49_PWR2.1 | length 58.2
  Top Layer w10: R49_PWR2.1@4556.38,190 4556.38,133.78 Q2_PWR2.1@4557.76,132.4
NetQ2_PWR2_3: Q2_PWR2.3 R48_PWR2.2 R52_PWR2.1 R53_PWR2.2 U12_PWR2.2 | length 583.8
  Top Layer w10: U12_PWR2.2@4252.6,117.2 4256.46,113.35 4279.32,113.35 4283.18,109.49 4399.13,109.49 R48_PWR2.2@4400,108.62 ; R52_PWR2.1@4451.38,260 4425,233.62 4425,192.86 4400,167.86 R53_PWR2.2@4400,166.38 R48_PWR2.2@4400,108.62 ; Q2_PWR2.3@4652.24,95 4533.13,95 4516.75,111.38 4402.76,111.38 R48_PWR2.2@4400,108.62
NetQ3_PWR1_3: Q3_PWR1.3 R47_PWR1.2 U12_PWR1.5 | length 141.1
  Top Layer w10: R47_PWR1.2@4018.62,1135 4021.5,1137.87 4021.5,1205 4021.5,1205.34 4050.68,1234.53 4073.54,1234.53 U12_PWR1.5@4077.4,1238.39
NetQ3_PWR2_3: Q3_PWR2.3 R47_PWR2.2 U12_PWR2.5 | length 141.1
  Top Layer w10: R47_PWR2.2@4018.62,65 4021.5,67.87 4021.5,135 4021.5,135.34 4050.68,164.53 4073.54,164.53 U12_PWR2.5@4077.4,168.39
NetQ4_PWR1_3: Q4_PWR1.3 R57_PWR1.2 | length 188.7
  Top Layer w10: R57_PWR1.2@4110,1521.38 4123.62,1535 4235,1535 4266.5,1503.5 Q4_PWR1.3@4280,1503.5
NetQ4_PWR2_3: Q4_PWR2.3 R57_PWR2.2 | length 188.7
  Top Layer w10: R57_PWR2.2@4110,451.38 4123.62,465 4235,465 4266.5,433.5 Q4_PWR2.3@4280,433.5
NetQ5_PWR1_3: Q5_PWR1.3 R66_PWR1.1 | length 204.8
  Top Layer w10: R66_PWR1.1@4103.62,1830 4106.87,1830 4141.87,1865 4238.13,1865 4271.64,1831.5 Q5_PWR1.3@4280,1831.5
NetQ5_PWR2_3: Q5_PWR2.3 R66_PWR2.1 | length 204.8
  Top Layer w10: R66_PWR2.1@4103.62,760 4106.87,760 4141.87,795 4238.13,795 4271.64,761.5 Q5_PWR2.3@4280,761.5
NetR1_ADC1_2: R1_ADC1.2 U2_ADC1.1 U3_ADC1.2 | length 2243.1
  Top Layer w6: v1(4055,2000) 4060,2000 4061.61,2001.61 U2_ADC1.1@4111.14,2001.61 4111.14,1948.86 4165,1895 R1_ADC1.2@4186.38,1895
  Bottom Layer w6: v1(4055,2000) 4010.58,2000 3967.13,2043.45 3967.13,2066.55 4017.58,2117 5808,2117 U3_ADC1.2@5840,2085
NetR1_ADC2_2: R1_ADC2.2 U2_ADC2.1 U3_ADC2.2 | length 2244
  Top Layer w6: v1(4055,927.74) 4060,927.74 4061.61,929.36 4111.14,929.36 4111.14,876.6 ; 4111.14,878.86 4165,825 R1_ADC2.2@4186.38,825
  Bottom Layer w6: v1(4055,927.74) 4010.58,927.74 3967.13,971.2 3967.13,994.29 4019.84,1047 5808,1047 U3_ADC2.2@5840,1015
NetR2_ADC1_2: R2_ADC1.2 R8_ADC1.1 U2_ADC1.5 | length 140
  Top Layer w6: R2_ADC1.2@3793.62,2040 R8_ADC1.1@3793.62,2090 3835,2090 3846.61,2078.39 U2_ADC1.5@3878.86,2078.39
NetR2_ADC2_2: R2_ADC2.2 R8_ADC2.1 U2_ADC2.5 | length 140
  Top Layer w6: R2_ADC2.2@3793.62,970 R8_ADC2.1@3793.62,1020 3835,1020 3846.61,1008.39 U2_ADC2.5@3878.86,1008.39
NetR4_ADC1_1: R4_ADC1.1 R5_ADC1.1 U2_ADC1.3 | length 156.3
  Top Layer w6: U2_ADC1.3@4111.14,2052.8 4117,2046.94 4138.02,2046.94 4149.57,2035.38 4149.57,2026.8 R5_ADC1.1@4186.38,1990 R4_ADC1.1@4186.38,1940
NetR4_ADC2_1: R4_ADC2.1 R5_ADC2.1 U2_ADC2.3 | length 179.5
  Top Layer w6: U2_ADC2.3@4090.13,982.8 U2_ADC2.3@4111.14,982.8 4117,976.94 4138.02,976.94 4149.57,965.38 4149.57,954.55 4186.38,917.74 R4_ADC2.1@4186.38,867.74
NetR5_ADC1_2: R5_ADC1.2 R6_ADC1.1 R9_ADC1.2 U2_ADC1.2 | length 426.1
  Top Layer w6: U2_ADC1.2@4111.14,2027.2 4073.38,2027.2 4027.13,2073.45 4027.13,2096.55 4043.45,2112.87 4066.55,2112.87 4081.3,2098.12 4186.38,2098.12 R6_ADC1.1@4186.38,2090 R9_ADC1.2@4186.38,2040 4233.62,1992.76 R5_ADC1.2@4233.62,1990
NetR5_ADC2_2: R5_ADC2.2 R6_ADC2.1 R9_ADC2.2 U2_ADC2.2 | length 422.6
  Top Layer w6: U2_ADC2.2@4111.14,954.95 4073.38,954.95 4027.13,1001.2 4027.13,1024.29 4043.45,1040.62 4071.06,1040.62 4083.56,1028.12 4178.26,1028.12 R6_ADC2.1@4186.38,1020 4186.38,967.74 4233.62,920.5 R5_ADC2.2@4233.62,917.74
NetR7_ADC1_2: R7_ADC1.2 U2_ADC1.6 U3_ADC1.1 | length 2237.8
  Top Layer w6: R7_ADC1.2@3793.62,1990 3856.42,2052.8 U2_ADC1.6@3878.86,2052.8 3992.8,2052.8 v1(3995,2055)
  Bottom Layer w6: v1(3995,2055) 4077.25,2055 4125.12,2102.87 5576.55,2102.87 5576.71,2102.71 5746.02,2102.71 5808.06,2040.66 5837.8,2040.66 5838.46,2040 5895,2040 U3_ADC1.1@5940,2085
NetR7_ADC2_2: R7_ADC2.2 U2_ADC2.6 U3_ADC2.1 | length 2237.8
  Top Layer w6: R7_ADC2.2@3793.62,920 U2_ADC2.6@3856.42,982.8 ; U2_ADC2.6@3856.42,980.54 3878.86,980.54 3992.8,980.54 v1(3995,982.74)
  Bottom Layer w6: v1(3995,982.74) 4077.25,982.74 4125.12,1030.62 ; 4125.12,1032.87 5576.55,1032.87 5576.71,1032.71 5746.02,1032.71 5808.06,970.66 5837.8,970.66 5838.46,970 5895,970 U3_ADC2.1@5940,1015
NetR10_ADC1_2: R10_ADC1.2 U6_ADC1.20 | length 450
  Top Layer w6: v1(5025,1660) 5025,1605 5058.39,1571.61 U6_ADC1.20@5091.14,1571.61 ; v1(5025,1780) 5025,1805 5002.31,1827.68 5002.31,1933.87 5024.25,1955.81 R10_ADC1.2@5025,1955.81
  Bottom Layer w6: v1(5025,1660) v1(5025,1780)
NetR10_ADC2_2: R10_ADC2.2 U6_ADC2.20 | length 450
  Top Layer w6: v1(5025,590) 5025,535 5058.39,501.61 U6_ADC2.20@5091.14,501.61 ; v1(5025,710) 5025,735 5002.31,757.68 5002.31,863.87 5024.25,885.81 R10_ADC2.2@5025,885.81
  Bottom Layer w6: v1(5025,590) v1(5025,710)
NetR12_ADC1_1: R12_ADC1.1 U5_ADC1.3 | length 1035.3
  Top Layer w6: v1(4565,1890) 4636.61,1961.61 U5_ADC1.3@4666.14,1961.61 ; v1(5145,1370) 5156.38,1370 R12_ADC1.1@5171.38,1355
  Bottom Layer w6: v1(4565,1890) 4598.01,1923.01 4651.99,1923.01 4922.13,1652.87 4926.55,1652.87 4942.87,1636.55 4942.87,1632.13 5030.98,1544.02 5050.45,1544.02 5066.78,1527.7 5066.78,1508.22 5145,1430 v1(5145,1370)
NetR12_ADC2_1: R12_ADC2.1 U5_ADC2.3 | length 1035.3
  Top Layer w6: v1(4565,820) 4636.61,891.61 U5_ADC2.3@4666.14,891.61 ; v1(5145,300) 5156.38,300 R12_ADC2.1@5171.38,285
  Bottom Layer w6: v1(4565,820) 4598.01,853.01 4651.99,853.01 4922.13,582.87 4926.55,582.87 4942.87,566.55 4942.87,562.13 5030.98,474.02 5050.45,474.02 5066.78,457.7 5066.78,438.22 5145,360 v1(5145,300)
NetR13_ADC1_1: R13_ADC1.1 U5_ADC1.7 | length 1131.6
  Top Layer w6: U5_ADC1.7@4666.14,2063.98 4711.02,2063.98 v1(4720,2055) ; v1(5240,2040) 5311.7,2111.7 5705,2111.7 5721.7,2095 R13_ADC1.1@5736.38,2095
  Bottom Layer w6: v1(4720,2055) 4752.87,2022.13 5222.13,2022.13 v1(5240,2040)
NetR13_ADC2_1: R13_ADC2.1 U5_ADC2.7 | length 1131.6
  Top Layer w6: U5_ADC2.7@4666.14,993.98 4711.02,993.98 v1(4720,985) ; v1(5240,970) 5311.7,1041.7 5705,1041.7 5721.7,1025 R13_ADC2.1@5736.38,1025
  Bottom Layer w6: v1(4720,985) 4752.87,952.13 5222.13,952.13 v1(5240,970)
NetR36_2: R36.2 U11.3 | length 217.5
  Top Layer w10: R36.2@275.01,468.64 275.01,550.01 332.8,607.8 U11.3@387.2,607.8
NetR41_1: R41.1 R44.2 U10.7 | length 120.3
  Top Layer w10: U10.7@1490.28,1055.32 1521.06,1055.32 R41.1@1540,1036.38 R44.2@1540,973.62
NetR63_PWR1_1: R63_PWR1.1 U15_PWR1.4 | length 104.2
  Top Layer w6: R63_PWR1.1@2828.62,1795 2828.82,1794.8 U15_PWR1.4@2932.76,1794.8
NetR63_PWR2_1: R63_PWR2.1 U15_PWR2.4 | length 94.3
  Top Layer w6: R63_PWR2.1@2838.43,734.8 U15_PWR2.4@2932.76,734.8
NetR64_PWR1_1: R64_PWR1.1 R67_PWR1.2 U15_PWR1.3 | length 202.4
  Top Layer w6: R67_PWR1.2@2828.62,1705 R64_PWR1.1@2828.62,1750 2850.74,1772.12 2947.12,1772.12 2964.25,1789.25 U15_PWR1.3@2964.25,1794.8
NetR64_PWR2_1: R64_PWR2.1 R67_PWR2.2 U15_PWR2.3 | length 206.6
  Top Layer w6: R67_PWR2.2@2828.62,635 R64_PWR2.1@2828.62,680 2860.74,712.12 2947.12,712.12 2964.25,729.25 U15_PWR2.3@2964.25,734.8
NetU7_3: U7.3 U8.3 U9.1 | length 282.2
  Top Layer w6: U7.3@552.8,492.24 552.8,472.2 565,460 610.58,460 633.45,482.87 688.46,482.87 U9.1@690.72,480.61 U8.3@690.71,589.41
NetU7_7: U7.7 U8.1 U9.6 | length 478.7
  Top Layer w10: U7.7@527.2,647.76 527.2,612.8 535,605 v1(535,600) ; v1(635,665) 655.13,644.87 690.71,644.87 U8.1@690.71,640.59 715.49,640.61 720.33,635.76 720.33,611 740.02,591.31 740.02,493.62 753.03,480.61 U9.6@779.31,480.61
  Bottom Layer w10: v1(535,600) 579.98,600 584.98,605 635,655.01 v1(635,665)
SPI_A: J9.28 R29.2 U8.6 | length 1840.3
  Top Layer w10: R29.2@766.51,715.01 779.31,702.22 U8.6@779.29,640.59 ; R29.2@771.51,720.01 869.98,720.01 1020,570 v1(2075,570)
  Bottom Layer w10: J9.28@2075,175 v1(2075,570)
SPI_B: J9.42 R33.2 U9.3 | length 2228.2
  Top Layer w10: U9.3@695.72,424.42 U9.3@690.72,429.42 690.72,375.65 R33.2@711.38,355 756.38,310 2640,310 J9.42@2775,175
SPI_CLK: J9.31 U1_ADC1.3 U1_ADC2.3 | length 3178.8
  Top Layer w10: v1(2270,1000) v1(3050,1000) ; v1(3153.32,983.32) 3155,985 3202.75,985 3207.63,989.87 3235.37,989.87 3236.05,989.19 3236.33,989.19 3243.45,982.07 3272.72,982.07 U1_ADC2.3@3272.72,977.82 ; 3202.63,2049.87 3272.72,2049.87 U1_ADC1.3@3272.72,2047.82
  Bottom Layer w10: v1(2270,1000) 2270,300 2325,245 2325,125 J9.31@2275,75 ; v1(3050,1000) 3050,1005 3071.68,983.32 v1(3153.32,983.32) 3153.32,1021.07 3179.87,1047.63 3179.87,1790.13 3154.87,1815.13 3154.87,1837.37 3145,1847.25 3145,1937.75 3149.87,1942.63 3149.87,1967.37 3149.87,1972.37 3145,1977.25 3145,2005 v1@3187.5,2047.5
  other v1: 3185,2050
SPI_CS1: U1_ADC1.5 U4_ADC1.1 U8.4 | length 3730
  Top Layer w6: v1(3050,1975) 3056.29,1975 3113.18,2031.9 3161.9,2031.9 3162.79,2032.79 3175.59,2019.99 U4_ADC1.1@3175.59,2004.29 ; U4_ADC1.1@3182.07,1997.82 3197.77,1997.82 3203.45,1992.13 3226.55,1992.13 3232.23,1997.82 U1_ADC1.5@3272.72,1997.82
  Top Layer w10: U8.4@779.29,589.41 801.23,589.41 850.64,540 1083.71,540 1083.83,540.13 2109.87,540.13 2110,540 v1(2115,540)
  Bottom Layer w10: v1(2115,540) 2115.13,540.13 2115.13,937.37 2245,1067.25 2245,1645 2255,1655 2297.5,1655 2297.63,1655.13 2322.37,1655.13 2339.87,1672.63 2339.87,1685 2645,1685 2870,1910 2985,1910 v1(3050,1975)
SPI_CS2: U1_ADC2.5 U4_ADC2.1 U9.4 | length 3085.6
  Top Layer w6: U4_ADC2.1@3175.59,934.29 3195.71,934.29 v1(3215,915) 3227.82,927.82 U1_ADC2.5@3272.72,927.82
  Top Layer w10: U9.4@779.31,429.42 801.22,429.42 837,393.64 905.89,393.64 907.25,395 v1(2145,395) ; v1(2145,915) 3035,915 3040,910 v1(3050,910)
  Bottom Layer w6: v1(3050,910) 3210,910 v1(3215,915)
  Bottom Layer w10: v1(2145,395) v1(2145,915)
SPI_ISO_CLK_ADC1: U1_ADC1.14 U6_ADC1.11 | length 1660.5
  Top Layer w6: U1_ADC1.14@3487.28,2047.82 3530.63,2047.82 v4(3540,2038.44) ; v1@4784.42,1475 4829.85,1520.43 U6_ADC1.11@4858.86,1520.43 ; v1@4785,1475.58 v1(4785,1480)
  Bottom Layer w6: v4(3540,2038.44) 3586.18,2038.44 3721.87,1902.75 4047.25,1902.75 4147.13,1802.87 4212.87,1802.87 4310.75,1705 4409.62,1705 4670.75,1443.87 4748.87,1443.87 v1(4785,1480)
SPI_ISO_CLK_ADC2: U1_ADC2.14 U6_ADC2.11 | length 1662
  Top Layer w6: U1_ADC2.14@3487.28,977.82 3530.63,977.82 v4(3540,968.44) ; v1@4784.42,405 4829.85,450.43 U6_ADC2.11@4858.86,450.43 ; v1@4785,405.58 v1(4785,410)
  Bottom Layer w6: v4(3540,968.44) 3586.18,968.44 3721.87,832.75 3950.96,832.75 3952.71,831 3987.29,831 3989.04,832.75 4047.25,832.75 4147.13,732.87 4212.87,732.87 4310.75,635 4409.62,635 4670.75,373.87 4748.87,373.87 v1(4785,410)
